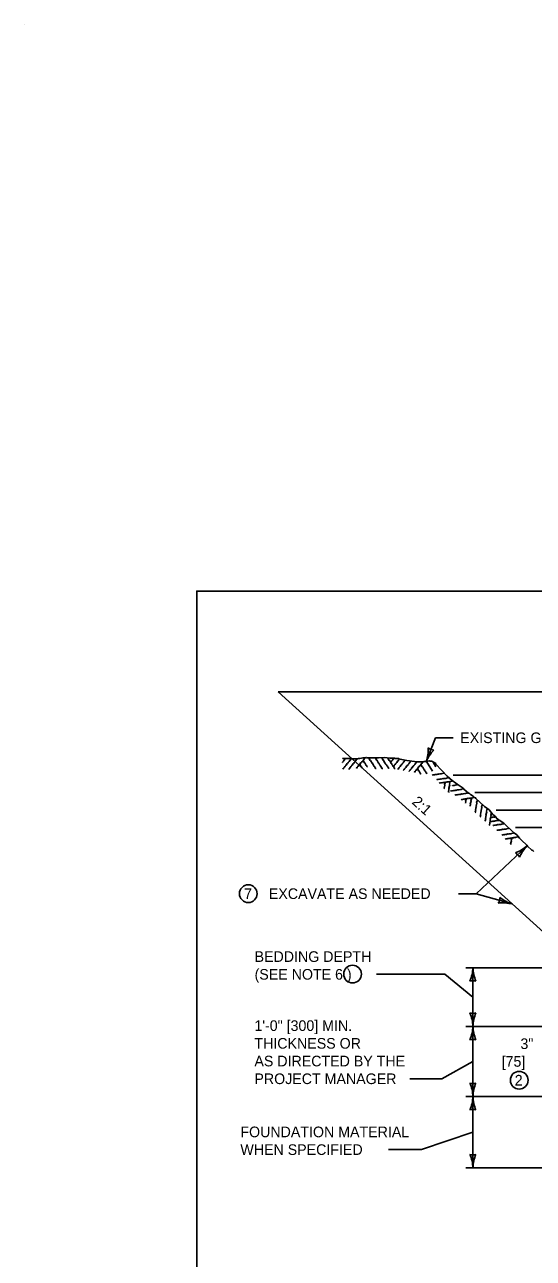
# Model space of a CAD drawing. Extents: x 49991.4 to 50021, y 49987.6 to 50011.4.
# Drawn here: x 50008.76 to 50011.64, y 50004.4 to 50011.36 of the extents above; entities that cross this region are included whole.
import ezdxf

# ---------------------------------------------------------------- set-up
doc = ezdxf.new("R2010")
doc.units = 0
for name, color, linetype in [('Level 1', 7, 'Continuous'), ('Level 2', 7, 'Continuous'), ('Level 3', 7, 'Continuous')]:
    doc.layers.add(name, color=color, linetype=linetype)

msp = doc.modelspace()

# ---------------------------------------------------------------- linework, layer by layer
at = {"layer": 'Level 1'}
for p, q in [((50008.7646, 50011.3628), (50008.7646, 50011.3628)), ((50011.9161, 50006.0384), (50010.1966, 50007.5958)), ((50013.8839, 50007.5958), (50010.1966, 50007.5958)), ((50010.8445, 50007.221), (50010.8566, 50007.221)), ((50011.0355, 50007.2032), (50011.0683, 50007.1477)), ((50011.0725, 50007.1988), (50011.0885, 50007.1722)), ((50011.1866, 50007.1266), (50013.4832, 50007.1266)), ((50011.3074, 50007.0276), (50013.4832, 50007.0276)), ((50011.4295, 50006.9286), (50012.7377, 50006.9286)), ((50011.5371, 50006.8296), (50012.5045, 50006.8296))]:
    msp.add_line(p, q, dxfattribs=at)
msp.add_lwpolyline([(50020.9378, 50008.1646), (50009.7374, 50008.1646), (50009.7374, 49999.8856), (50020.9378, 49999.8856)], close=True, dxfattribs=at)
for points in [[(50010.56, 50007.2214), (50010.5648, 50007.2202), (50010.6053, 50007.2202), (50010.6111, 50007.2183), (50010.6458, 50007.2183), (50010.6516, 50007.2202), (50010.6593, 50007.2202), (50010.6766, 50007.2241), (50010.6882, 50007.2241), (50010.694, 50007.226), (50010.6979, 50007.2241), (50010.7576, 50007.2241), (50010.7634, 50007.2241), (50010.7962, 50007.226), (50010.829, 50007.2221), (50010.8502, 50007.2221), (50010.8559, 50007.2202), (50010.8694, 50007.2202), (50010.8771, 50007.2202), (50010.8771, 50007.2183), (50010.9234, 50007.2086), (50010.9832, 50007.2009), (50011.014, 50007.2009), (50011.0218, 50007.2029), (50011.0333, 50007.2029)], [(50010.5745, 50007.2202), (50010.5764, 50007.2183), (50010.5706, 50007.2106), (50010.5706, 50007.2087), (50010.5687, 50007.2087), (50010.5667, 50007.2048), (50010.561, 50007.1991), (50010.561, 50007.1971), (50010.56, 50007.1971)], [(50010.6068, 50007.2192), (50010.6087, 50007.2173), (50010.6029, 50007.2096), (50010.6029, 50007.2077), (50010.601, 50007.2077), (50010.599, 50007.2038), (50010.5933, 50007.1981), (50010.5933, 50007.1961), (50010.5913, 50007.1961), (50010.5894, 50007.1923), (50010.5855, 50007.1903), (50010.5836, 50007.1845), (50010.5797, 50007.1826), (50010.5797, 50007.1807), (50010.5759, 50007.1768), (50010.5759, 50007.1749), (50010.574, 50007.1749), (50010.5721, 50007.171), (50010.5701, 50007.171), (50010.5701, 50007.1691), (50010.5662, 50007.1653), (50010.5662, 50007.1633), (50010.5643, 50007.1633), (50010.5624, 50007.1595)], [(50010.64, 50007.2183), (50010.6419, 50007.2164), (50010.6361, 50007.2087), (50010.6361, 50007.2067), (50010.6342, 50007.2067), (50010.6323, 50007.2029), (50010.6265, 50007.1971), (50010.6265, 50007.1951), (50010.6246, 50007.1951), (50010.6226, 50007.1913), (50010.6188, 50007.1893), (50010.6169, 50007.1836), (50010.613, 50007.1816), (50010.613, 50007.1797), (50010.6091, 50007.1759), (50010.6091, 50007.1739), (50010.6072, 50007.1739), (50010.6053, 50007.1701), (50010.6034, 50007.1701), (50010.6034, 50007.1682), (50010.5995, 50007.1643), (50010.5995, 50007.1624), (50010.5975, 50007.1624), (50010.5956, 50007.1585)], [(50010.6843, 50007.2241), (50010.6863, 50007.2221), (50010.6805, 50007.2144), (50010.6805, 50007.2125), (50010.6785, 50007.2125), (50010.6766, 50007.2087), (50010.6708, 50007.2029), (50010.6708, 50007.2009), (50010.6689, 50007.2009), (50010.667, 50007.1971), (50010.6631, 50007.1951), (50010.6612, 50007.1893), (50010.6573, 50007.1874), (50010.6573, 50007.1855), (50010.6535, 50007.1816), (50010.6535, 50007.1797), (50010.6516, 50007.1797), (50010.6496, 50007.1759), (50010.6477, 50007.1759), (50010.6477, 50007.1739), (50010.6439, 50007.1701), (50010.6439, 50007.1682), (50010.6419, 50007.1682), (50010.64, 50007.1643)], [(50010.7099, 50007.2236), (50010.7157, 50007.2101), (50010.7195, 50007.2082), (50010.7272, 50007.1927), (50010.7292, 50007.1927), (50010.7311, 50007.1889), (50010.7311, 50007.187), (50010.7349, 50007.1831), (50010.7388, 50007.1754), (50010.7407, 50007.1754), (50010.7465, 50007.1638), (50010.7504, 50007.1638)], [(50010.747, 50007.2241), (50010.7528, 50007.2106), (50010.7566, 50007.2087), (50010.7643, 50007.1932), (50010.7663, 50007.1932), (50010.7682, 50007.1893), (50010.7682, 50007.1874), (50010.7721, 50007.1836), (50010.7759, 50007.1759), (50010.7778, 50007.1759), (50010.7836, 50007.1643), (50010.7875, 50007.1643)], [(50010.7832, 50007.225), (50010.7889, 50007.2115), (50010.7928, 50007.2096), (50010.8005, 50007.1942), (50010.8024, 50007.1942), (50010.8043, 50007.1903), (50010.8043, 50007.1884), (50010.8082, 50007.1845), (50010.8121, 50007.1768), (50010.814, 50007.1768), (50010.8198, 50007.1653), (50010.8236, 50007.1653)], [(50010.8174, 50007.2231), (50010.8231, 50007.2096), (50010.827, 50007.2077), (50010.8347, 50007.1923), (50010.8366, 50007.1923), (50010.8386, 50007.1884), (50010.8386, 50007.1865), (50010.8425, 50007.1826), (50010.8463, 50007.1749), (50010.8482, 50007.1749), (50010.854, 50007.1633), (50010.8579, 50007.1633)], [(50010.8498, 50007.2193), (50010.8463, 50007.2159), (50010.8463, 50007.2139), (50010.8443, 50007.2139), (50010.8425, 50007.2101), (50010.8405, 50007.2101), (50010.8405, 50007.2082), (50010.8366, 50007.2043), (50010.8366, 50007.2024), (50010.8347, 50007.2024), (50010.8328, 50007.1985)], [(50010.6578, 50007.1879), (50010.6636, 50007.1744), (50010.6675, 50007.1725), (50010.6712, 50007.165)], [(50010.6776, 50007.2105), (50010.6834, 50007.1971), (50010.6872, 50007.1951), (50010.6949, 50007.1797), (50010.6969, 50007.1797), (50010.6988, 50007.1759), (50010.6988, 50007.1739), (50010.7024, 50007.1704)], [(50010.8811, 50007.2146), (50010.8795, 50007.213), (50010.8795, 50007.2111), (50010.8776, 50007.2111), (50010.8757, 50007.2072), (50010.8719, 50007.2053), (50010.8699, 50007.1995), (50010.866, 50007.1976), (50010.866, 50007.1956), (50010.8622, 50007.1918), (50010.8622, 50007.1898), (50010.8603, 50007.1898), (50010.8583, 50007.186), (50010.8564, 50007.186), (50010.8564, 50007.1841), (50010.8526, 50007.1802), (50010.8526, 50007.1783), (50010.8506, 50007.1783), (50010.8487, 50007.1744)], [(50010.9109, 50007.2106), (50010.9128, 50007.2087), (50010.907, 50007.2009), (50010.907, 50007.199), (50010.9051, 50007.199), (50010.9031, 50007.1951), (50010.8974, 50007.1893), (50010.8974, 50007.1874), (50010.8954, 50007.1874), (50010.8935, 50007.1836), (50010.8897, 50007.1816), (50010.8877, 50007.1759), (50010.8839, 50007.1739), (50010.8839, 50007.172), (50010.88, 50007.1682), (50010.88, 50007.1663), (50010.8781, 50007.1663), (50010.8761, 50007.1624), (50010.8743, 50007.1624), (50010.8743, 50007.1604), (50010.8736, 50007.1598)], [(50010.9432, 50007.2053), (50010.9451, 50007.2033), (50010.9393, 50007.1956), (50010.9393, 50007.1937), (50010.9374, 50007.1937), (50010.9354, 50007.1898), (50010.9297, 50007.1841), (50010.9297, 50007.1821), (50010.9278, 50007.1821), (50010.9258, 50007.1783), (50010.9219, 50007.1764), (50010.92, 50007.1705), (50010.9162, 50007.1686), (50010.9162, 50007.1667), (50010.9123, 50007.1628), (50010.9123, 50007.1609), (50010.9104, 50007.1609), (50010.9084, 50007.1571), (50010.9065, 50007.1571), (50010.9065, 50007.1551), (50010.9026, 50007.1513)], [(50010.9769, 50007.2019), (50010.9788, 50007.2), (50010.973, 50007.1923), (50010.973, 50007.1903), (50010.9711, 50007.1903), (50010.9692, 50007.1865), (50010.9634, 50007.1807), (50010.9634, 50007.1788), (50010.9615, 50007.1788), (50010.9595, 50007.1749), (50010.9557, 50007.173), (50010.9537, 50007.1672), (50010.9499, 50007.1653), (50010.9499, 50007.1633), (50010.946, 50007.1595), (50010.946, 50007.1576), (50010.9441, 50007.1576), (50010.9422, 50007.1537), (50010.9403, 50007.1537), (50010.9403, 50007.1518), (50010.9364, 50007.1479), (50010.9364, 50007.1473)], [(50011.0116, 50007.2014), (50011.0135, 50007.1995), (50011.0078, 50007.1918), (50011.0078, 50007.1898), (50011.0058, 50007.1898), (50011.0039, 50007.186), (50010.9981, 50007.1802), (50010.9981, 50007.1783), (50010.9962, 50007.1783), (50010.9942, 50007.1744), (50010.9904, 50007.1725), (50010.9885, 50007.1667), (50010.9846, 50007.1648), (50010.9846, 50007.1628), (50010.9808, 50007.159), (50010.9808, 50007.1571), (50010.9788, 50007.1571), (50010.9769, 50007.1532), (50010.975, 50007.1532), (50010.975, 50007.1513), (50010.9711, 50007.1474), (50010.9711, 50007.1455), (50010.9692, 50007.1455), (50010.9673, 50007.1416)], [(50010.9846, 50007.1638), (50010.9904, 50007.1503), (50010.9943, 50007.1484), (50011.002, 50007.133), (50011.0039, 50007.133), (50011.005, 50007.1307)], [(50011.0039, 50007.1865), (50011.0097, 50007.173), (50011.0135, 50007.171), (50011.0212, 50007.1556), (50011.0231, 50007.1556), (50011.0251, 50007.1517), (50011.0251, 50007.1498), (50011.0289, 50007.146), (50011.0328, 50007.1383), (50011.0347, 50007.1383), (50011.0369, 50007.1339)], [(50011.0867, 50007.1919), (50011.0879, 50007.1908), (50011.0866, 50007.1894), (50011.1221, 50007.1513), (50011.1527, 50007.1205), (50011.1665, 50007.1078), (50011.18, 50007.0953), (50011.201, 50007.08)], [(50011.134, 50007.1397), (50011.1341, 50007.1369), (50011.1247, 50007.1351), (50011.1234, 50007.1336), (50011.122, 50007.1349), (50011.118, 50007.1333), (50011.1098, 50007.1329), (50011.1085, 50007.1314), (50011.1071, 50007.1327), (50011.1031, 50007.1311), (50011.0989, 50007.1323), (50011.0936, 50007.1292), (50011.0895, 50007.1304), (50011.0882, 50007.1289), (50011.0827, 50007.1286), (50011.0815, 50007.1272), (50011.08, 50007.1285), (50011.076, 50007.1269), (50011.0746, 50007.1282), (50011.0733, 50007.1267), (50011.0678, 50007.1264)], [(50011.1596, 50007.1142), (50011.1598, 50007.1114), (50011.1503, 50007.1095), (50011.149, 50007.1081), (50011.1476, 50007.1094), (50011.1435, 50007.1078), (50011.1354, 50007.1073), (50011.1341, 50007.1059), (50011.1327, 50007.1072), (50011.1286, 50007.1056), (50011.1245, 50007.1067), (50011.1192, 50007.1037), (50011.115, 50007.1049), (50011.1137, 50007.1034), (50011.1083, 50007.1031), (50011.107, 50007.1017), (50011.1056, 50007.103), (50011.1016, 50007.1014), (50011.1001, 50007.1027), (50011.0989, 50007.1012), (50011.0934, 50007.1009), (50011.093, 50007.1004)], [(50011.18, 50007.0953), (50011.1802, 50007.0926), (50011.1708, 50007.0907), (50011.1695, 50007.0892), (50011.168, 50007.0905), (50011.164, 50007.089), (50011.1559, 50007.0885), (50011.1546, 50007.0871), (50011.1531, 50007.0884), (50011.1491, 50007.0868), (50011.145, 50007.0879), (50011.1397, 50007.0849), (50011.1355, 50007.086), (50011.1342, 50007.0845), (50011.1288, 50007.0843), (50011.1275, 50007.0828), (50011.1261, 50007.0841), (50011.1221, 50007.0825), (50011.1206, 50007.0838), (50011.1193, 50007.0824), (50011.1139, 50007.0821), (50011.1126, 50007.0806), (50011.1112, 50007.0819), (50011.1072, 50007.0803)], [(50011.1423, 50007.0864), (50011.1376, 50007.0725), (50011.1392, 50007.0684), (50011.1347, 50007.0518), (50011.1361, 50007.0505), (50011.1355, 50007.0481)], [(50011.1695, 50007.0892), (50011.1648, 50007.0753), (50011.1664, 50007.0713), (50011.1619, 50007.0546), (50011.1633, 50007.0534), (50011.1622, 50007.0492), (50011.1609, 50007.0478), (50011.1612, 50007.0424), (50011.1589, 50007.034), (50011.1604, 50007.0327), (50011.1591, 50007.028)], [(50011.201, 50007.08), (50011.2081, 50007.0741), (50011.2429, 50007.0522), (50011.2459, 50007.0469), (50011.2718, 50007.0237), (50011.2773, 50007.0214), (50011.2831, 50007.0162), (50011.2986, 50007.0075), (50011.3072, 50006.9998), (50011.3128, 50006.9974), (50011.3144, 50006.9933), (50011.3589, 50006.9535), (50011.3632, 50006.9496), (50011.389, 50006.9292), (50011.4108, 50006.9045), (50011.4266, 50006.8904), (50011.4296, 50006.8851), (50011.4397, 50006.8761), (50011.4454, 50006.871), (50011.4711, 50006.8543), (50011.5271, 50006.8012), (50011.5454, 50006.7897), (50011.5612, 50006.7707), (50011.569, 50006.762), (50011.5704, 50006.7599)], [(50011.2433, 50007.0505), (50011.2434, 50007.0478), (50011.234, 50007.0459), (50011.2327, 50007.0445), (50011.2313, 50007.0457), (50011.2273, 50007.0442), (50011.2191, 50007.0437), (50011.2178, 50007.0423), (50011.2164, 50007.0436), (50011.2124, 50007.042), (50011.2082, 50007.0431), (50011.2029, 50007.0401), (50011.1987, 50007.0413), (50011.1974, 50007.0398), (50011.192, 50007.0395), (50011.1907, 50007.0381), (50011.1893, 50007.0393), (50011.1853, 50007.0377), (50011.1838, 50007.039), (50011.1825, 50007.0376), (50011.1771, 50007.0373), (50011.1758, 50007.0359), (50011.1744, 50007.0371), (50011.1704, 50007.0356)], [(50011.2081, 50007.0741), (50011.2082, 50007.0714), (50011.1988, 50007.0695), (50011.1975, 50007.0681), (50011.196, 50007.0693), (50011.192, 50007.0678), (50011.1839, 50007.0673), (50011.1826, 50007.0659), (50011.1818, 50007.0665)], [(50011.2674, 50007.0277), (50011.2676, 50007.025), (50011.2581, 50007.023), (50011.2568, 50007.0216), (50011.2554, 50007.0229), (50011.2514, 50007.0213), (50011.2432, 50007.0208), (50011.2419, 50007.0194), (50011.2405, 50007.0207), (50011.2365, 50007.0191), (50011.2323, 50007.0202), (50011.227, 50007.0172), (50011.2228, 50007.0183), (50011.2216, 50007.0169), (50011.2161, 50007.0166), (50011.2148, 50007.0152), (50011.2134, 50007.0165), (50011.2094, 50007.0149), (50011.208, 50007.0162), (50011.2067, 50007.0147), (50011.2012, 50007.0144), (50011.2, 50007.013), (50011.1985, 50007.0143), (50011.1945, 50007.0127)], [(50011.3043, 50007.0024), (50011.3044, 50006.9997), (50011.295, 50006.9978), (50011.2937, 50006.9963), (50011.2923, 50006.9977), (50011.2883, 50006.996), (50011.2801, 50006.9956), (50011.2788, 50006.9941), (50011.2774, 50006.9954), (50011.2734, 50006.9938), (50011.2692, 50006.995), (50011.2639, 50006.992), (50011.2598, 50006.9931), (50011.2585, 50006.9917), (50011.253, 50006.9913), (50011.2518, 50006.9899), (50011.2504, 50006.9912), (50011.2463, 50006.9896), (50011.2449, 50006.9909), (50011.2436, 50006.9895), (50011.2382, 50006.9892), (50011.2369, 50006.9877), (50011.2354, 50006.989), (50011.2314, 50006.9874)], [(50011.2604, 50006.9931), (50011.2558, 50006.9792), (50011.2574, 50006.9752), (50011.2552, 50006.9672)], [(50011.2903, 50006.9968), (50011.2856, 50006.9829), (50011.2872, 50006.9789), (50011.2827, 50006.9623), (50011.2841, 50006.961), (50011.283, 50006.9568), (50011.2817, 50006.9554), (50011.282, 50006.9504)], [(50011.323, 50006.985), (50011.3183, 50006.9711), (50011.3199, 50006.9671), (50011.3154, 50006.9504), (50011.3168, 50006.9491), (50011.3157, 50006.945), (50011.3144, 50006.9436), (50011.3147, 50006.9381), (50011.3124, 50006.9298), (50011.3139, 50006.9285), (50011.3105, 50006.916), (50011.3134, 50006.9134)], [(50011.351, 50006.9606), (50011.3463, 50006.9467), (50011.3479, 50006.9427), (50011.3434, 50006.926), (50011.3448, 50006.9248), (50011.3437, 50006.9206), (50011.3424, 50006.9192), (50011.3427, 50006.9137), (50011.3404, 50006.9054), (50011.3418, 50006.9041), (50011.3385, 50006.8916), (50011.3414, 50006.8891)], [(50011.3786, 50006.9372), (50011.3739, 50006.9233), (50011.3755, 50006.9193), (50011.371, 50006.9027), (50011.3724, 50006.9014), (50011.3713, 50006.8972), (50011.37, 50006.8958), (50011.3703, 50006.8903), (50011.368, 50006.882), (50011.3695, 50006.8807), (50011.3661, 50006.8683), (50011.3689, 50006.8657)], [(50011.4028, 50006.913), (50011.3981, 50006.899), (50011.3997, 50006.895), (50011.3952, 50006.8784), (50011.3966, 50006.8771), (50011.3955, 50006.873), (50011.3942, 50006.8715), (50011.3945, 50006.8661), (50011.3922, 50006.8577), (50011.3936, 50006.8565), (50011.3902, 50006.844), (50011.3931, 50006.8414)], [(50011.4454, 50006.871), (50011.4432, 50006.8708), (50011.4419, 50006.8694), (50011.4404, 50006.8707), (50011.4365, 50006.8691), (50011.4323, 50006.8702), (50011.427, 50006.8672), (50011.4228, 50006.8683), (50011.4215, 50006.8669), (50011.4161, 50006.8666), (50011.4148, 50006.8652), (50011.4134, 50006.8664), (50011.4094, 50006.8649), (50011.408, 50006.8661), (50011.4067, 50006.8647), (50011.4012, 50006.8644), (50011.3999, 50006.863), (50011.3985, 50006.8643), (50011.3945, 50006.8626)], [(50011.4266, 50006.8904), (50011.4217, 50006.8901), (50011.4204, 50006.8886), (50011.419, 50006.89), (50011.415, 50006.8884), (50011.4136, 50006.8897), (50011.4122, 50006.8882), (50011.4068, 50006.888), (50011.4055, 50006.8865), (50011.4041, 50006.8878), (50011.4001, 50006.8862)], [(50011.4711, 50006.8543), (50011.4713, 50006.8516), (50011.4618, 50006.8497), (50011.4605, 50006.8483), (50011.4591, 50006.8495), (50011.455, 50006.8479), (50011.4469, 50006.8474), (50011.4456, 50006.846), (50011.4442, 50006.8474), (50011.4402, 50006.8457), (50011.436, 50006.8468), (50011.4307, 50006.8439), (50011.4265, 50006.845), (50011.4253, 50006.8436), (50011.4198, 50006.8433), (50011.4185, 50006.8418), (50011.4171, 50006.8431), (50011.4131, 50006.8415), (50011.4117, 50006.8428), (50011.4104, 50006.8413), (50011.4095, 50006.8413)], [(50011.4991, 50006.8277), (50011.4993, 50006.825), (50011.4898, 50006.8231), (50011.4885, 50006.8217), (50011.4871, 50006.823), (50011.4831, 50006.8214), (50011.4749, 50006.8209), (50011.4736, 50006.8195), (50011.4722, 50006.8208), (50011.4682, 50006.8192), (50011.464, 50006.8203), (50011.4587, 50006.8173), (50011.4546, 50006.8184), (50011.4533, 50006.817), (50011.4478, 50006.8166), (50011.4466, 50006.8152), (50011.4451, 50006.8165), (50011.4411, 50006.815), (50011.4397, 50006.8162), (50011.4384, 50006.8148), (50011.4329, 50006.8145)], [(50011.5271, 50006.8012), (50011.5273, 50006.7985), (50011.5178, 50006.7966), (50011.5165, 50006.7951), (50011.5151, 50006.7964), (50011.5111, 50006.7948), (50011.503, 50006.7944), (50011.5016, 50006.7929), (50011.5002, 50006.7942), (50011.4962, 50006.7926), (50011.492, 50006.7938), (50011.4867, 50006.7907), (50011.4826, 50006.7919), (50011.4813, 50006.7904), (50011.4758, 50006.7902), (50011.4745, 50006.7887), (50011.4731, 50006.79), (50011.4691, 50006.7884), (50011.4677, 50006.7897), (50011.4664, 50006.7882), (50011.4609, 50006.7879), (50011.4605, 50006.7875)], [(50011.5533, 50006.7802), (50011.5535, 50006.7774), (50011.544, 50006.7755), (50011.5427, 50006.7741), (50011.5413, 50006.7754), (50011.5373, 50006.7738), (50011.5291, 50006.7734), (50011.5278, 50006.7719), (50011.5264, 50006.7732), (50011.5224, 50006.7716), (50011.5182, 50006.7728), (50011.5129, 50006.7697), (50011.5088, 50006.7709), (50011.5075, 50006.7694), (50011.502, 50006.7691), (50011.5008, 50006.7677), (50011.4993, 50006.769), (50011.4953, 50006.7674), (50011.4939, 50006.7687), (50011.4926, 50006.7672), (50011.4871, 50006.7669), (50011.4858, 50006.7655), (50011.4844, 50006.7668), (50011.4804, 50006.7652)], [(50011.5182, 50006.7728), (50011.5135, 50006.7589), (50011.5151, 50006.7548), (50011.5106, 50006.7382), (50011.512, 50006.7369), (50011.5114, 50006.7345)], [(50011.569, 50006.762), (50011.5718, 50006.7579), (50011.602, 50006.7309), (50011.605, 50006.7256), (50011.6309, 50006.7024), (50011.6365, 50006.7), (50011.6423, 50006.6949)]]:
    msp.add_lwpolyline(points, dxfattribs=at)
msp.add_spline([(50011.0333, 50007.2029), (50011.0503, 50007.2058), (50011.0746, 50007.1994), (50011.0879, 50007.1908)], degree=3, dxfattribs=at)
at = {"layer": 'Level 2'}
for centre in [(50010.0283, 50006.4567), (50010.6171, 50006.0027), (50011.5589, 50005.4035)]:
    msp.add_circle(centre, 0.05, dxfattribs=at)
at = {"layer": 'Level 3'}
for p, q in [((50011.0857, 50007.3369), (50011.0333, 50007.2029)), ((50011.0857, 50007.3369), (50011.1858, 50007.3369)), ((50011.3156, 50006.4567), (50011.6043, 50006.7268)), ((50011.2156, 50006.4567), (50011.3156, 50006.4567)), ((50011.3156, 50006.4567), (50011.5185, 50006.3985)), ((50011.8761, 50006.0384), (50011.2575, 50006.0384)), ((50011.2975, 50006.0384), (50011.2975, 50005.7076)), ((50010.7524, 50006.0014), (50011.1395, 50006.0014)), ((50011.2975, 50005.873), (50011.1395, 50006.0014)), ((50012.7687, 50005.7076), (50011.2575, 50005.7076)), ((50011.2975, 50005.7076), (50011.2975, 50005.3117)), ((50011.2975, 50005.5096), (50011.1222, 50005.4117)), ((50010.9407, 50005.4117), (50011.1222, 50005.4117)), ((50011.8761, 50005.3117), (50011.2575, 50005.3117)), ((50011.2975, 50005.3117), (50011.2975, 50004.9089)), ((50011.0068, 50005.0117), (50011.2975, 50005.1103)), ((50010.8208, 50005.0117), (50011.0068, 50005.0117)), ((50011.854, 50004.9089), (50011.2575, 50004.9089))]:
    msp.add_line(p, q, dxfattribs=at)
for centre, radius, start, end in [((50010.8231, 50007.2753), 0.2223, 340.98229, 1.1658), ((50011.2458, 50007.1073), 0.233, 136.54465, 155.7945), ((50011.08, 50007.3223), 0.0548, 230.76063, 266.48299), ((50011.4592, 50006.8953), 0.2223, 290.55379, 310.7373), ((50011.5107, 50006.6392), 0.0548, 25.2366, 60.95896), ((50011.7717, 50006.5648), 0.233, 135.92509, 155.17494), ((50011.3953, 50006.4338), 0.0548, 326.14259, 1.86495), ((50011.4655, 50006.1716), 0.233, 76.83108, 96.08093), ((50011.5886, 50006.6095), 0.2223, 231.45978, 251.64329), ((50011.0753, 50006.0476), 0.2223, 337.45601, 357.63952), ((50011.5302, 50006.0499), 0.233, 182.82731, 202.07716), ((50011.2975, 50005.9102), 0.0548, 72.13882, 107.86118), ((50011.2975, 50005.8358), 0.0548, 252.13882, 287.86118), ((50011.0648, 50005.6961), 0.233, 2.82731, 22.07716), ((50011.5196, 50005.6985), 0.2223, 157.45601, 177.63952), ((50011.0753, 50005.7168), 0.2223, 337.45601, 357.63952), ((50011.5302, 50005.7191), 0.233, 182.82731, 202.07716), ((50011.2975, 50005.5794), 0.0548, 72.13882, 107.86118), ((50011.2975, 50005.4399), 0.0548, 252.13882, 287.86118), ((50011.0648, 50005.3002), 0.233, 2.82731, 22.07716), ((50011.5196, 50005.3025), 0.2223, 157.45601, 177.63952), ((50011.0753, 50005.3208), 0.2223, 337.45601, 357.63952), ((50011.5302, 50005.3231), 0.233, 182.82731, 202.07716), ((50011.2975, 50005.1834), 0.0548, 72.13882, 107.86118), ((50011.2975, 50005.0371), 0.0548, 252.13882, 287.86118), ((50011.0648, 50004.8974), 0.233, 2.82731, 22.07716), ((50011.5196, 50004.8997), 0.2223, 157.45601, 177.63952)]:
    msp.add_arc(centre, radius, start, end, dxfattribs=at)

# ---------------------------------------------------------------- texts
at = {"layer": 'Level 2'}
for s, p in [('EXISTING GROUND', (50011.2258, 50007.3069)), ('7', (50010.0045, 50006.4267)), ('EXCAVATE AS NEEDED', (50010.1444, 50006.4267)), ('BEDDING DEPTH', (50010.0638, 50006.0714)), ('(SEE NOTE 6 )', (50010.0638, 50005.9714)), ('1\'-0" [300] MIN.', (50010.0628, 50005.6817)), ('THICKNESS OR', (50010.0628, 50005.5817)), ('3" ', (50011.5657, 50005.5796)), ('AS DIRECTED BY THE', (50010.0628, 50005.4817)), ('[75]', (50011.4598, 50005.4796)), ('PROJECT MANAGER', (50010.0628, 50005.3817)), ('2', (50011.5337, 50005.3735)), ('FOUNDATION MATERIAL', (50009.9835, 50005.0817)), ('WHEN SPECIFIED', (50009.9835, 50004.9817))]:
    msp.add_text(s, height=0.06, dxfattribs=at).set_placement(p)
msp.add_text('2:1', height=0.06, rotation=317.83247, dxfattribs=at).set_placement((50010.9483, 50006.9689))

doc.saveas('drawing.dxf')
